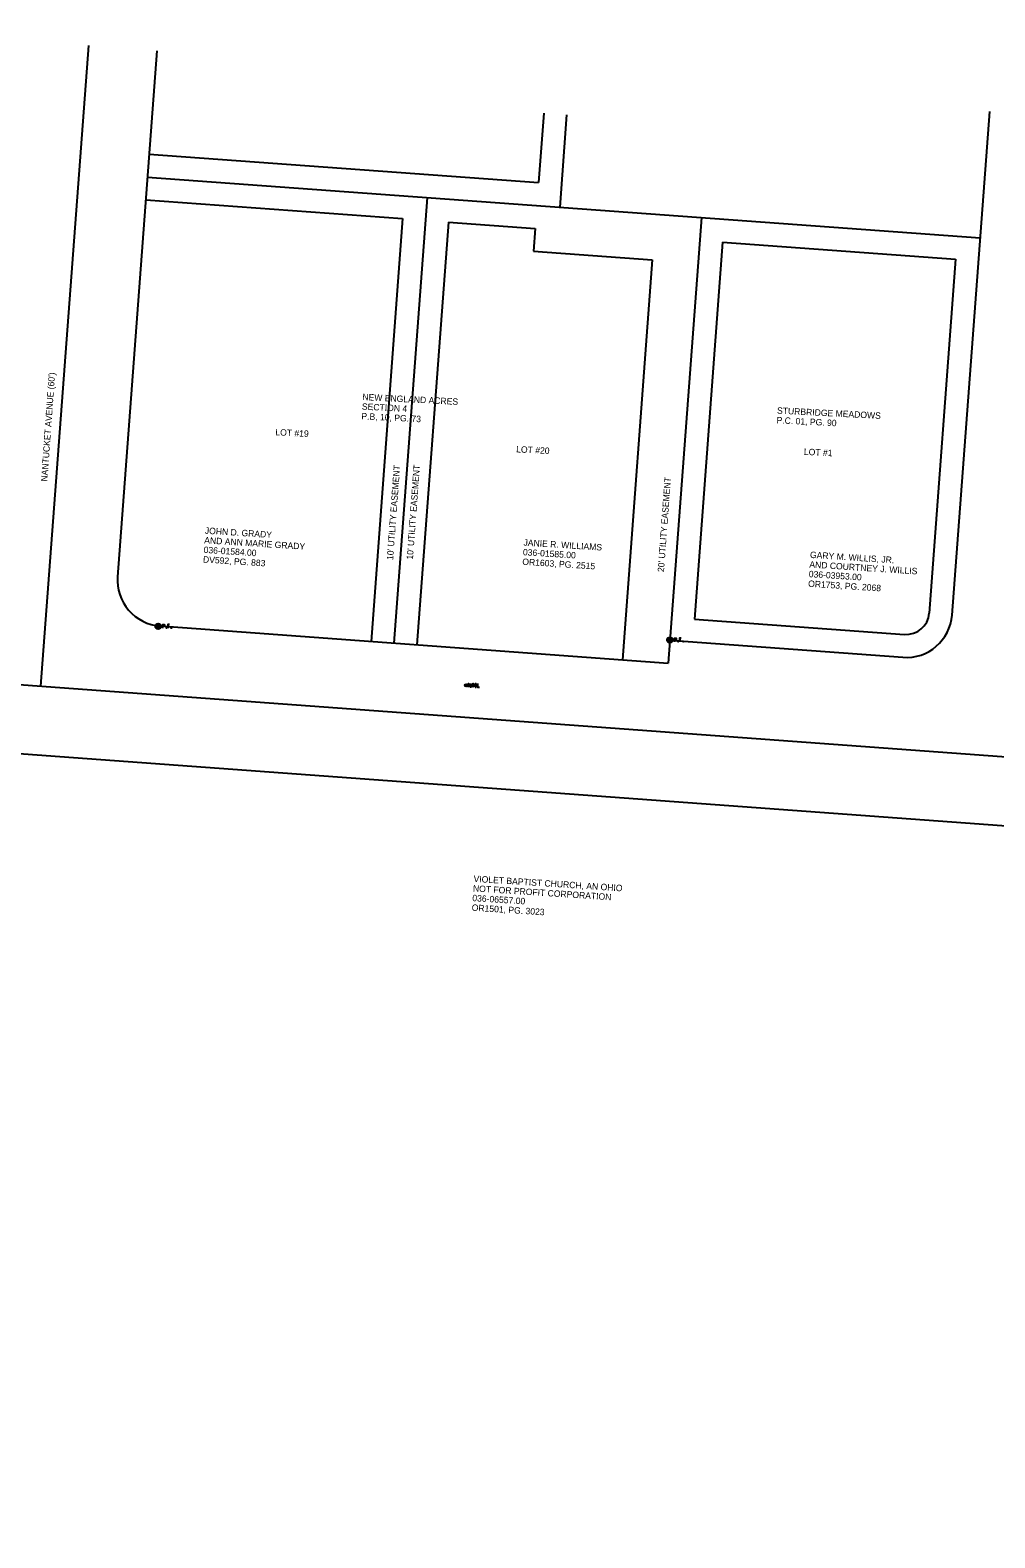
# Model space of a CAD drawing. Extents: x 1898254 to 1901377, y 701554 to 704886.
# Drawn here: x 1900647 to 1901068, y 702797 to 703455 of the extents above; entities that cross this region are included whole.
import ezdxf

# ---------------------------------------------------------------- set-up
doc = ezdxf.new("R2010")
doc.units = 0
for name, color, linetype in [('DV_X_Property_Line', 7, 'Continuous'), ('DV_X_Text', 7, 'Continuous'), ('RW_X_CL', 7, 'Continuous'), ('RW_X_Esmt_SH', 7, 'Continuous'), ('RW_X_Esmt_U', 7, 'Continuous'), ('RW_X_Fee_RW', 7, 'Continuous'), ('RW_X_Text', 7, 'Continuous'), ('SC_Scratch2', 7, 'Continuous'), ('SV_X_Control_Cells_Found', 7, 'Continuous'), ('SV_X_Mon_Cells_Found', 7, 'Continuous')]:
    doc.layers.add(name, color=color, linetype=linetype)

msp = doc.modelspace()

# ---------------------------------------------------------------- linework, layer by layer
at = {"layer": 'DV_X_Property_Line'}
for p, q in [((1900881.34, 703418.11), (1900878.32, 703377.77)), ((1900698.38, 703390.92), (1901061.83, 703364.35)), ((1900820.48, 703382), (1900805.96, 703187.54)), ((1900940.16, 703373.25), (1900925.64, 703178.79))]:
    msp.add_line(p, q, dxfattribs=at)
at = {"layer": 'RW_X_CL'}
for p, q in [((1900672.58, 703448.26), (1900651.7, 703168.73)), ((1899815.76, 703229.84), (1901162.17, 703131.42))]:
    msp.add_line(p, q, dxfattribs=at)
at = {"layer": 'RW_X_Esmt_SH'}
msp.add_line((1900608.03, 703141.85), (1901159.98, 703101.5), dxfattribs=at)
at = {"layer": 'RW_X_Esmt_U'}
for p, q in [((1900871.36, 703418.85), (1900869.1, 703388.47)), ((1900699.11, 703400.89), (1900869.1, 703388.47)), ((1900697.65, 703380.95), (1900809.76, 703372.75)), ((1900809.76, 703372.75), (1900795.98, 703188.27)), ((1900829.71, 703371.29), (1900815.93, 703186.81)), ((1900829.71, 703371.29), (1900867.61, 703368.52)), ((1900867.61, 703368.52), (1900866.86, 703358.55)), ((1900949.39, 703362.55), (1900937.1, 703198)), ((1900949.39, 703362.55), (1901051.12, 703355.11)), ((1900866.86, 703358.55), (1900918.72, 703354.76)), ((1900918.72, 703354.76), (1900905.69, 703180.25)), ((1901051.12, 703355.11), (1901039.57, 703200.52)), ((1900937.1, 703198), (1901028.87, 703191.3))]:
    msp.add_line(p, q, dxfattribs=at)
msp.add_arc((1901029.6, 703201.27), 10, 265.81918, 355.7289, dxfattribs=at)
at = {"layer": 'RW_X_Fee_RW'}
for p, q in [((1900702.5, 703446.02), (1900685.35, 703216.44)), ((1901065.96, 703419.55), (1901049.54, 703199.78)), ((1900703.84, 703195), (1900925.64, 703178.79)), ((1900926.38, 703188.76), (1901028.14, 703181.32))]:
    msp.add_line(p, q, dxfattribs=at)
for centre, start, end in [((1900705.29, 703214.95), 175.7289, 265.81918), ((1901029.6, 703201.27), 265.81918, 355.7289)]:
    msp.add_arc(centre, 20, start, end, dxfattribs=at)
at = {"layer": 'SC_Scratch2'}
msp.add_circle((1899815.76, 703229.84), 1561.35, dxfattribs=at)
at = {"layer": 'SV_X_Control_Cells_Found'}
for p, q in [((1900837.1, 703169.44), (1900837.8, 703168.73)), ((1900837.1, 703168.73), (1900837.8, 703169.44))]:
    msp.add_line(p, q, dxfattribs=at)
for points in [[(1900838.54, 703168.28), (1900838.54, 703169.88), (1900839.49, 703168.28), (1900839.49, 703169.88)], [(1900839.99, 703168.28), (1900840.49, 703169.88), (1900840.98, 703168.28)], [(1900840.86, 703168.65), (1900840.11, 703168.65)], [(1900841.49, 703169.88), (1900841.89, 703169.88)], [(1900841.69, 703168.28), (1900841.69, 703169.88)], [(1900842.39, 703169.88), (1900842.39, 703168.28), (1900843.26, 703168.28)], [(1900841.49, 703168.28), (1900841.89, 703168.28)]]:
    msp.add_lwpolyline(points, dxfattribs=at)
msp.add_circle((1900837.45, 703169.09), 0.5, dxfattribs=at)
at = {"layer": 'SV_X_Mon_Cells_Found'}
for points in [[(1900705.04, 703194.06), (1900705.04, 703195.66), (1900705.57, 703195.66), (1900705.63, 703195.64), (1900705.7, 703195.62), (1900705.74, 703195.59), (1900705.77, 703195.57), (1900705.82, 703195.51), (1900705.85, 703195.44), (1900705.87, 703195.34), (1900705.87, 703195.19), (1900705.86, 703195.14), (1900705.84, 703195.06), (1900705.79, 703194.98), (1900705.75, 703194.94), (1900705.72, 703194.91), (1900705.66, 703194.89), (1900705.57, 703194.88), (1900705.04, 703194.88)], [(1900708.05, 703195.66), (1900707.29, 703195.66), (1900707.29, 703194.06)], [(1900706.69, 703194.27), (1900706.74, 703194.27), (1900706.77, 703194.25), (1900706.81, 703194.19), (1900706.81, 703194.13), (1900706.77, 703194.08), (1900706.74, 703194.06), (1900706.69, 703194.06), (1900706.65, 703194.08), (1900706.62, 703194.13), (1900706.62, 703194.19), (1900706.65, 703194.25), (1900706.69, 703194.27)], [(1900707.29, 703194.88), (1900707.83, 703194.88)], [(1900708.84, 703194.27), (1900708.89, 703194.27), (1900708.92, 703194.25), (1900708.96, 703194.19), (1900708.96, 703194.13), (1900708.92, 703194.08), (1900708.89, 703194.06), (1900708.84, 703194.06), (1900708.8, 703194.08), (1900708.77, 703194.13), (1900708.77, 703194.19), (1900708.8, 703194.25), (1900708.84, 703194.27)], [(1900928.39, 703188.12), (1900928.39, 703189.72), (1900928.92, 703189.72), (1900928.97, 703189.7), (1900929.05, 703189.68), (1900929.08, 703189.65), (1900929.12, 703189.63), (1900929.16, 703189.56), (1900929.19, 703189.5), (1900929.22, 703189.4), (1900929.22, 703189.25), (1900929.21, 703189.2), (1900929.18, 703189.12), (1900929.14, 703189.04), (1900929.1, 703189), (1900929.06, 703188.97), (1900929.01, 703188.95), (1900928.92, 703188.93), (1900928.39, 703188.93)], [(1900930.03, 703188.33), (1900930.09, 703188.33), (1900930.12, 703188.3), (1900930.15, 703188.25), (1900930.15, 703188.19), (1900930.12, 703188.14), (1900930.09, 703188.12), (1900930.03, 703188.12), (1900930, 703188.14), (1900929.97, 703188.19), (1900929.97, 703188.25), (1900930, 703188.3), (1900930.03, 703188.33)], [(1900931.4, 703189.72), (1900930.64, 703189.72), (1900930.64, 703188.12)], [(1900930.64, 703188.93), (1900931.18, 703188.93)], [(1900932.18, 703188.33), (1900932.24, 703188.33), (1900932.27, 703188.3), (1900932.3, 703188.25), (1900932.3, 703188.19), (1900932.27, 703188.14), (1900932.24, 703188.12), (1900932.18, 703188.12), (1900932.15, 703188.14), (1900932.12, 703188.19), (1900932.12, 703188.25), (1900932.15, 703188.3), (1900932.18, 703188.33)]]:
    msp.add_lwpolyline(points, dxfattribs=at)
for centre, radius in [((1900703.05, 703194.86), 1.2), ((1900703.05, 703194.86), 0.495), ((1900926.39, 703188.92), 1.2), ((1900926.39, 703188.92), 0.495)]:
    msp.add_circle(centre, radius, dxfattribs=at)

# ---------------------------------------------------------------- texts
at = {"layer": 'DV_X_Text'}
for s, rotation, p in [('NEW ENGLAND ACRES', 357.09486, (1900792.14, 703293.59)), ('P.B, 10, PG. 73', 357.09486, (1900791.72, 703285.2)), ('SECTION 4', 357.09486, (1900791.93, 703289.4)), ('STURBRIDGE MEADOWS', 357.09486, (1900973.12, 703287.66)), ('LOT #19', 357.09486, (1900754.16, 703278.23)), ('P.C. 01, PG. 90', 357.09486, (1900972.91, 703283.46)), ('LOT #20', 357.09486, (1900859.26, 703270.76)), ('LOT #1', 357.09486, (1900984.84, 703269.68)), ("10' UTILITY EASEMENT", 85.7139, (1900805.6, 703223.7)), ("10' UTILITY EASEMENT", 85.7139, (1900814.25, 703223.87)), ("20' UTILITY EASEMENT", 85.7139, (1900923.81, 703218.44)), ('JOHN D. GRADY ', 356.3351, (1900723.37, 703235.27)), ('036-01584.00', 356.3351, (1900722.83, 703226.89)), ('AND ANN MARIE GRADY', 356.3351, (1900723.1, 703231.08)), ('036-01585.00', 356.3351, (1900862.2, 703225.89)), ('JANIE R. WILLIAMS', 356.3351, (1900862.46, 703230.08)), ('DV592, PG. 883', 356.3351, (1900722.56, 703222.7)), ('OR1603, PG. 2515', 356.3351, (1900861.93, 703221.7)), ('AND COURTNEY J. WILLIS', 356.3351, (1900987.22, 703220.52)), ('GARY M. WILLIS, JR.', 356.3351, (1900987.49, 703224.71)), ('OR1753, PG. 2068', 356.3351, (1900986.69, 703212.13)), ('036-03953.00', 356.3351, (1900986.96, 703216.33)), ('VIOLET BAPTIST CHURCH, AN OHIO', 356.3351, (1900840.65, 703083.33)), ('036-06557.00', 356.3351, (1900840.11, 703074.95)), ('NOT FOR PROFIT CORPORATION', 356.3351, (1900840.38, 703079.14)), ('OR1501, PG. 3023', 356.3351, (1900839.85, 703070.76))]:
    msp.add_text(s, height=2.8, rotation=rotation, dxfattribs=at).set_placement(p)
at = {"layer": 'RW_X_Text'}
msp.add_text("NANTUCKET AVENUE (60')", height=2.8, rotation=85.93252, dxfattribs=at).set_placement((1900654.7, 703257.94))

doc.saveas('drawing.dxf')
